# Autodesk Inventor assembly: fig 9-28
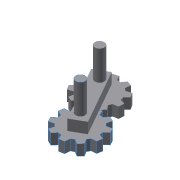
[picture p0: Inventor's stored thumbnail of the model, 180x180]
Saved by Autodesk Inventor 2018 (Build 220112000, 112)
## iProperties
Created: 2017-05
Part Number: fig 9-28
Document SubType Name: Assembly
Designer: CADCIM 00
Author: CADCIM 00
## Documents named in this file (3)
- E:\_Deepak\Inventor\Autodesk Inventor_2017_Project\Resources\Inventor_2018_Part\c09_Inv_2018\c09_inv_2018_prt\fig 9-28.iam
- E:\_Deepak\Inventor\Autodesk Inventor_2017_Project\Resources\Inventor_2018_Part\c09_Inv_2018\c09_inv_2018_prt\1.ipt
- E:\_Deepak\Inventor\Autodesk Inventor_2017_Project\Resources\Inventor_2018_Part\c09_Inv_2018\c09_inv_2018_prt\2.ipt
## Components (3 placed, 2 different names)
1. 1:1 — Flush:1, Rotation:1, Insert:2
2. 1:2 — Flush:1, Rotation:1, Insert:1
3. 2:1 — Insert:1, Insert:2
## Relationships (4: Insert 2, Flush 1, RelateRotation 1)
- Flush:1: 1:1 ↔ 1:2
- Rotation:1 [RelateRotation]: 1:1 ↔ 1:2
- Insert:1: 1:2 ↔ 2:1
- Insert:2: 1:1 ↔ 2:1
